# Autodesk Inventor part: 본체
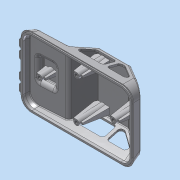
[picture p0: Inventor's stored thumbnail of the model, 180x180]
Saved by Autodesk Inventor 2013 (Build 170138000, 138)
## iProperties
Created: 2015-05
Part Number: 본체
Material: ABS 플라스틱
Document SubType Name: Modeling
Designer: Administrator
Density: 1.06 g/cm^3
Mass: 33.5971 g
Surface Area: 312.398 cm^2
Volume: 31.6954 cm^3
Author: Administrator
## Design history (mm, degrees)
sketch "스케치1"
  geometry: L1 (-60, 0)-(60, 0); L2 (-60, 0)-(-60, 1); L3 (-60, 1)-(60, 1); L4 (60, 1)-(60, 0); L5 (60, 1)-(61, 1); L6 (61, 1)-(58.321, 11); L7 (58.321, 11)-(28.321, 31); L8 (-58.856, 9)-(-19, 11.089); L9 (-19, 11.089)-(-6.558, 31); L10 (-6.558, 31)-(28.321, 31); L11 (-58.856, 9)-(-61, 1); L12 (-61, 1)-(-60, 1); 3 further points
  constraints: 24 end point, 3 parallel, 3 perpendicular, 2 coincident, 2 midpoint, 1 horizontal
  dimensions: "d9" = 120 distance of L1.start L1.end; "d10" = 1 distance of L3.end L1.end; "d11" = 105 deg angle of L6 L1; "d13" = 30 horizontal distance of L6.end L7.end; "d14" = 20 vertical distance of L6.end L7.end; "d15" = 1 distance of L3.end L5.end; "d25" = 1 distance of L11.end L2.end; "d27" = 125 deg angle of L9 L8; "d28" = 3 deg angle of L3 L8; "d29" = 42 horizontal distance of L8.end L11.end; "d30" = 31 distance between parallel lines of L1 L10; "d31" = 9 vertical distance of L1.start L8.start; "d32" = 105 deg angle of L11 L1
extrude "돌출1" new body sketch "스케치1" stored distance "d33" = 76; taper "d34" = 0 deg
extrude "돌출2" join sketch "스케치1" stored distance "d35" = 74; taper "d36" = 0 deg
sketch "스케치3"
  geometry: L1 (1, 38)-(31, 29.962); L2 (1, -38)-(31, -29.962); L3 (31, -38)-(1, -38) reference; L4 (1, -38)-(1, -37) reference; L5 (1, -37)-(0, -37) reference; L6 (0, -37)-(0, 37) reference; L7 (0, 37)-(1, 37) reference; L8 (1, 37)-(1, 38) reference; L9 (1, 38)-(31, 38) reference; L10 (31, 38)-(31, -38) reference; 1 further point
  constraints: 4 end point, 2 point on line
  dimensions: "d41" = 105 deg angle of L2 L6
extrude "돌출4" cut sketch "스케치3" stored distance "d42" = 300; taper "d43" = 0 deg
fillet "모깎기5" dims "d72" = 12
fillet "모깎기6" dims "d73" = 12
fillet "모깎기7" dims "d74" = 3
fillet "모깎기8" dims "d75" = 3
feature "쉘2" dims "d76" = 2
sketch "스케치9"
  geometry: L1 (-36.17, 8.186)-(-36.17, 57.845) reference; L2 (-29.909, 46.016)-(-9.909, 46.016); L3 (-9.909, 46.016)-(-9.909, 20.016); L4 (-9.909, 20.016)-(-29.909, 20.016); L5 (-29.909, 20.016)-(-29.909, 46.016); L6 (-40.909, 59.424)-(-40.909, 6.607) reference; 3 further points
  constraints: 8 end point, 2 midpoint, 2 parallel, 1 horizontal, 1 horizontal alignment, 1 perpendicular
  dimensions: "d77" = 20 distance of L2.start L2.end; "d79" = 26 distance of L4.end L2.start; "d80" = 11 distance between parallel lines of L5 L6
extrude "돌출9" join sketch "스케치9" distance "d81" = 5; taper "d82" = -20 deg
fillet "모깎기9" dims "d83" = 3
fillet "모깎기10" dims "d84" = 3
fillet "모깎기11" dims "d85" = 3
sketch "스케치10"
  geometry: L1 (-60, 1)-(-61, 1) reference; L2 (-61, 1)-(-59.421, 6.895) reference; L3 (-56.68, 9.114)-(-52.525, 9.332) reference; L4 (-49.813, 11.451)-(-49.486, 12.521) reference; L5 (-46.774, 14.64)-(-34.632, 15.276) reference; L6 (-31.713, 13.453)-(-31.276, 12.422) reference; L7 (-28.357, 10.598)-(-20.56, 11.007) reference; L8 (-18.172, 12.413)-(-7.439, 29.59) reference; L9 (-4.895, 31)-(27.412, 31) reference; L10 (29.076, 30.496)-(57.38, 11.627) reference; L11 (58.613, 9.908)-(61, 1) reference; L12 (61, 1)-(60, 1) reference; L13 (60, 1)-(60, 0) reference; L14 (60, 0)-(58, 0) reference; L15 (58, 0)-(58, 3) reference; L16 (58, 3)-(58.394, 3) reference; L17 (58.394, 3)-(56.681, 9.39) reference; L18 (56.27, 9.963)-(27.967, 28.832) reference; L19 (27.412, 29)-(-4.895, 29) reference; L20 (-5.743, 28.53)-(-16.476, 11.353) reference; L21 (-20.455, 9.01)-(-56.575, 7.117) reference; L22 (-57.489, 6.377)-(-58.394, 3) reference; L23 (-58.394, 3)-(-58, 3) reference; L24 (-58, 3)-(-58, 0) reference; L25 (-58, 0)-(-60, 0) reference; L26 (-60, 0)-(-60, 1) reference; L27 (-13.16, 11)-(-3.787, 26); L28 (-3.787, 26)-(17.84, 26); L29 (17.84, 26)-(17.84, 11); L30 (17.84, 11)-(-13.16, 11); L31 (21.307, 26)-(26.807, 26); L32 (26.807, 26)-(49.307, 11); L33 (49.307, 11)-(21.307, 11); L34 (21.307, 11)-(21.307, 26); A1 r 3 centre (-56.523, 6.118) between (-56.68, 9.114) and (-59.421, 6.895) reference; A2 r 3 centre (-52.682, 12.328) between (-52.525, 9.332) and (-49.813, 11.451) reference; A3 r 3 centre (-46.617, 11.644) between (-46.774, 14.64) and (-49.486, 12.521) reference; A4 r 3 centre (-34.474, 12.281) between (-31.713, 13.453) and (-34.632, 15.276) reference; A5 r 3 centre (-28.514, 13.594) between (-31.276, 12.422) and (-28.357, 10.598) reference; A6 r 3 centre (-20.717, 14.003) between (-20.56, 11.007) and (-18.172, 12.413) reference; A7 r 3 centre (-4.895, 28) between (-4.895, 31) and (-7.439, 29.59) reference; A8 r 3 centre (27.412, 28) between (29.076, 30.496) and (27.412, 31) reference; A9 r 3 centre (55.715, 9.131) between (58.613, 9.908) and (57.38, 11.627) reference; A10 r 1 centre (55.715, 9.131) between (56.681, 9.39) and (56.27, 9.963) reference; A11 r 1 centre (27.412, 28) between (27.967, 28.832) and (27.412, 29) reference; A12 r 1 centre (-4.895, 28) between (-4.895, 29) and (-5.743, 28.53) reference; A13 r 5 centre (-20.717, 14.003) between (-20.455, 9.01) and (-16.476, 11.353) reference; A14 r 1 centre (-56.523, 6.118) between (-56.575, 7.117) and (-57.489, 6.377) reference; 1 further point
  constraints: 16 end point, 5 parallel, 3 perpendicular, 1 point on line
  dimensions: "d86" = 5 distance between parallel lines of L27 L8; "d87" = 5 distance between parallel lines of L28 L9; "d89" = 15 distance between parallel lines of L30 L28; "d90" = 31 distance of L29.end L27.start; "d91" = 5 distance between parallel lines of L10 L32; "d92" = 15 distance between parallel lines of L33 L31; "d93" = 28 distance of L32.end L33.end
extrude "돌출10" cut sketch "스케치10" stored distance "d94" = 300; taper "d95" = 0 deg
feature "쉘3" dims "d96" = 2
sketch "스케치13"
  geometry: L1 (65.895, 54.068)-(65.895, 1.251) reference; 2 further points
  constraints: 1 horizontal alignment, 1 other
  dimensions: "d103" = 50 distance from line of point (15.895, 27.66) L1
feature "엠보싱1" sketch "스케치13" dims "d104" = 0.5, "d105" = 0
fillet "모깎기12" dims "d117" = 3
fillet "모깎기13" dims "d118" = 3
sketch "스케치15"
  geometry: L1 (109, -63.409)-(109, -10.591) reference; C1 r 3 at (88, -37); C2 r 3 at (8, -37); C3 r 3 at (48, -15); C4 r 3 at (48, -59); 1 further point
  constraints: 4 centre point, 2 horizontal alignment, 1 vertical alignment
  dimensions: "d119" = 6 diameter of C1; "d120" = 6 diameter of C2; "d121" = 6 diameter of C3; "d122" = 6 diameter of C4; "d123" = 21 distance from line of L1 C1.centre; "d124" = 40 horizontal distance of C3.centre C1.centre; "d125" = 40 horizontal distance of C2.centre C3.centre; "d126" = 22 distance of point (48, -37) C3.centre; "d127" = 22 distance of C4.centre point (48, -37)
extrude "돌출13" join sketch "스케치15" stored distance "d128" = 300; taper "d129" = 2 deg
node "작업 평면4"
sketch "스케치16"
  geometry: L1 (-49.141, 15.732)-(49.141, 15.732) reference; L2 (60.732, 4.141)-(60.732, -48.141) reference; L3 (49.141, -59.732)-(-49.141, -59.732) reference; L4 (-60.732, -48.141)-(-60.732, 4.141) reference; L5 (48, 13)-(-48, 13) reference; L6 (-58, 3)-(-58, -47) reference; L7 (-48, -57)-(48, -57) reference; L8 (58, -47)-(58, 3) reference; L9 (-5, 1)-(5, 1); L10 (5, 1)-(5, -1); L11 (5, -1)-(-5, -1); L12 (-5, -1)-(-5, 1); L13 (-5, 1)-(5, -1); L14 (5, 1)-(-5, -1); C1 r 3.07 at (0, 0) reference; C2 r 3.07 at (40, -22) reference; C3 r 3.07 at (-40, -22) reference; C4 r 3.07 at (0, -44) reference; A1 r 10 centre (48, 3) between (58, 3) and (48, 13) reference; A2 r 10 centre (-48, 3) between (-48, 13) and (-58, 3) reference; A3 r 10 centre (-48, -47) between (-58, -47) and (-48, -57) reference; A4 r 10 centre (48, -47) between (48, -57) and (58, -47) reference; 5 further points; 4 other entities
  constraints: 12 end point, 2 midpoint, 2 parallel, 1 horizontal, 1 perpendicular, 4 other
  dimensions: "d131" = 2 distance of L9.end L10.end; "d133" = 10 distance of L9.start L9.end
extrude "돌출14" join sketch "스케치16" stored distance "d134" = 300; taper "d135" = 5 deg
sketch "스케치17"
  geometry: C1 r 3 at (0, 0) reference; 1 further point
node "작업 평면5"
sketch "스케치18"
  geometry: L1 (35, 23)-(37.098, 23) reference; L2 (45, 21)-(42.902, 21) reference; L3 (45, 23)-(45, 21) reference; L4 (42.902, 23)-(45, 23) reference; L5 (35, 21)-(35, 23) reference; L6 (37.098, 21)-(35, 21) reference; L7 (-9.141, 37.732)-(89.141, 37.732) reference; L8 (100.732, 26.141)-(100.732, -26.141) reference; L9 (89.141, -37.732)-(-9.141, -37.732) reference; L10 (-20.732, -26.141)-(-20.732, 26.141) reference; L11 (88, 35)-(-8, 35) reference; L12 (-18, 25)-(-18, -25) reference; L13 (-8, -35)-(88, -35) reference; L14 (98, -25)-(98, 25) reference; L15 (-5, 1)-(5, 1); L16 (5, 1)-(5, -1); L17 (5, -1)-(-5, -1); L18 (-5, -1)-(-5, 1); L19 (-5, 1)-(5, -1); L20 (5, 1)-(-5, -1); C1 r 3.07 at (80, 0) reference; C2 r 3.07 at (0, 0) reference; C3 r 3.07 at (40, -22) reference; A1 r 3.07 centre (40, 22) between (37.098, 23) and (37.098, 21) reference; A2 r 3.07 centre (40, 22) between (37.098, 21) and (42.902, 21) reference; A3 r 3.07 centre (40, 22) between (42.902, 21) and (42.902, 23) reference; A4 r 3.07 centre (40, 22) between (42.902, 23) and (37.098, 23) reference; A5 r 10 centre (88, 25) between (98, 25) and (88, 35) reference; A6 r 10 centre (-8, 25) between (-8, 35) and (-18, 25) reference; A7 r 10 centre (-8, -25) between (-18, -25) and (-8, -35) reference; A8 r 10 centre (88, -25) between (88, -35) and (98, -25) reference; 5 further points; 4 other entities
  constraints: 12 end point, 2 midpoint, 2 parallel, 1 horizontal, 1 perpendicular, 4 other
  dimensions: "d137" = 10 distance of L16.end L17.end; "d138" = 2 distance of L15.end L16.end
extrude "돌출15" join sketch "스케치18" stored distance "d139" = 300; taper "d140" = 5 deg
node "작업 평면6"
sketch "스케치19"
  geometry: L1 (-35, 21)-(-37.098, 21) reference; L2 (-42.902, 21)-(-45, 21) reference; L3 (-45, 21)-(-45, 23) reference; L4 (-45, 23)-(-42.902, 23) reference; L5 (-37.098, 23)-(-35, 23) reference; L6 (-35, 23)-(-35, 21) reference; L7 (-5, 45)-(-2.902, 45) reference; L8 (5, 43)-(2.902, 43) reference; L9 (5, 45)-(5, 43) reference; L10 (2.902, 45)-(5, 45) reference; L11 (-5, 43)-(-5, 45) reference; L12 (-2.902, 43)-(-5, 43) reference; L13 (-49.141, 59.732)-(49.141, 59.732) reference; L14 (60.732, 48.141)-(60.732, -4.141) reference; L15 (49.141, -15.732)-(-49.141, -15.732) reference; L16 (-60.732, -4.141)-(-60.732, 48.141) reference; L17 (48, 57)-(-48, 57) reference; L18 (-58, 47)-(-58, -3) reference; L19 (-48, -13)-(48, -13) reference; L20 (58, -3)-(58, 47) reference; L21 (-5, 1)-(5, 1); L22 (5, 1)-(5, -1); L23 (5, -1)-(-5, -1); L24 (-5, -1)-(-5, 1); L25 (-5, 1)-(5, -1); L26 (5, 1)-(-5, -1); C1 r 3.07 at (40, 22) reference; C2 r 3.07 at (0, 0) reference; A1 r 3.07 centre (-40, 22) between (-42.902, 21) and (-37.098, 21) reference; A2 r 3.07 centre (-40, 22) between (-37.098, 23) and (-42.902, 23) reference; A3 r 3.07 centre (-40, 22) between (-37.098, 21) and (-37.098, 23) reference; A4 r 3.07 centre (-40, 22) between (-42.902, 23) and (-42.902, 21) reference; A5 r 3.07 centre (0, 44) between (-2.902, 45) and (-2.902, 43) reference; A6 r 3.07 centre (0, 44) between (-2.902, 43) and (2.902, 43) reference; A7 r 3.07 centre (0, 44) between (2.902, 43) and (2.902, 45) reference; A8 r 3.07 centre (0, 44) between (2.902, 45) and (-2.902, 45) reference; A9 r 10 centre (48, 47) between (58, 47) and (48, 57) reference; A10 r 10 centre (-48, 47) between (-48, 57) and (-58, 47) reference; A11 r 10 centre (-48, -3) between (-58, -3) and (-48, -13) reference; A12 r 10 centre (48, -3) between (48, -13) and (58, -3) reference; 5 further points; 4 other entities
  constraints: 12 end point, 2 midpoint, 2 parallel, 1 horizontal, 1 perpendicular, 4 other
  dimensions: "d142" = 10 distance of L22.end L23.end; "d143" = 2 distance of L21.end L22.end
extrude "돌출16" join sketch "스케치19" stored distance "d144" = 300; taper "d145" = 5 deg
node "작업 평면7"
sketch "스케치20"
  geometry: L1 (-35, -23)-(-37.098, -23) reference; L2 (-42.902, -23)-(-45, -23) reference; L3 (-45, -23)-(-45, -21) reference; L4 (-45, -21)-(-42.902, -21) reference; L5 (-37.098, -21)-(-35, -21) reference; L6 (-35, -21)-(-35, -23) reference; L7 (-75, -1)-(-77.098, -1) reference; L8 (-82.902, -1)-(-85, -1) reference; L9 (-85, -1)-(-85, 1) reference; L10 (-85, 1)-(-82.902, 1) reference; L11 (-77.098, 1)-(-75, 1) reference; L12 (-75, 1)-(-75, -1) reference; L13 (-45, 23)-(-42.902, 23) reference; L14 (-35, 21)-(-37.098, 21) reference; L15 (-35, 23)-(-35, 21) reference; L16 (-37.098, 23)-(-35, 23) reference; L17 (-45, 21)-(-45, 23) reference; L18 (-42.902, 21)-(-45, 21) reference; L19 (-89.141, 37.732)-(9.141, 37.732) reference; L20 (20.732, 26.141)-(20.732, -26.141) reference; L21 (9.141, -37.732)-(-89.141, -37.732) reference; L22 (-100.732, -26.141)-(-100.732, 26.141) reference; L23 (8, 35)-(-88, 35) reference; L24 (-98, 25)-(-98, -25) reference; L25 (-88, -35)-(8, -35) reference; L26 (18, -25)-(18, 25) reference; L27 (-5, 1)-(5, 1); L28 (5, 1)-(5, -1); L29 (5, -1)-(-5, -1); L30 (-5, -1)-(-5, 1); L31 (-5, 1)-(5, -1); L32 (5, 1)-(-5, -1); C1 r 3.07 at (0, 0) reference; A1 r 3.07 centre (-40, -22) between (-42.902, -23) and (-37.098, -23) reference; A2 r 3.07 centre (-40, -22) between (-37.098, -21) and (-42.902, -21) reference; A3 r 3.07 centre (-40, -22) between (-37.098, -23) and (-37.098, -21) reference; A4 r 3.07 centre (-40, -22) between (-42.902, -21) and (-42.902, -23) reference; A5 r 3.07 centre (-80, 0) between (-82.902, -1) and (-77.098, -1) reference; A6 r 3.07 centre (-80, 0) between (-77.098, 1) and (-82.902, 1) reference; A7 r 3.07 centre (-80, 0) between (-77.098, -1) and (-77.098, 1) reference; A8 r 3.07 centre (-80, 0) between (-82.902, 1) and (-82.902, -1) reference; A9 r 3.07 centre (-40, 22) between (-42.902, 23) and (-42.902, 21) reference; A10 r 3.07 centre (-40, 22) between (-42.902, 21) and (-37.098, 21) reference; A11 r 3.07 centre (-40, 22) between (-37.098, 21) and (-37.098, 23) reference; A12 r 3.07 centre (-40, 22) between (-37.098, 23) and (-42.902, 23) reference; A13 r 10 centre (8, 25) between (18, 25) and (8, 35) reference; A14 r 10 centre (-88, 25) between (-88, 35) and (-98, 25) reference; A15 r 10 centre (-88, -25) between (-98, -25) and (-88, -35) reference; A16 r 10 centre (8, -25) between (8, -35) and (18, -25) reference; 5 further points; 4 other entities
  constraints: 12 end point, 2 midpoint, 2 parallel, 1 horizontal, 1 perpendicular, 4 other
  dimensions: "d147" = 10 distance of L28.end L29.end; "d148" = 2 distance of L27.end L28.end
extrude "돌출17" join sketch "스케치20" stored distance "d149" = 300; taper "d150" = 5 deg
sketch "스케치21"
  geometry: C1 r 3 at (0, 0) reference; C2 r 3 at (-40, -22) reference; C3 r 3 at (0, -44) reference; C4 r 3 at (40, -22) reference; 1 further point
hole "구멍1" sketch "스케치21" at (0, 0), (40, -22), (0, -44), (-40, -22) diameter "d151" = 3.242; stored, may be unused: countersink angle "d155" = 90 deg, drill point angle "d157" = 118 deg; dims "d152" = 9, "d153" = 4, "d154" = 2, "d156" = 11
node "작업 평면9"
  node "작업 평면8"
sketch "스케치22"
  geometry: A1 r 4 centre (-1, -21) between (-1, -17) and (-1, -25); A2 r 4 centre (-1, -10) between (-1, -6) and (-1, -14); A3 r 4 centre (-1, 10) between (-1, 14) and (-1, 6); A4 r 4 centre (-1, 21) between (-1, 25) and (-1, 17); 4 further points
  constraints: 8 point on circle, 4 centre point, 4 vertical alignment, 14 other
  dimensions: "d160" = 8 diameter of A1; "d161" = 8 diameter of A2; "d162" = 8 diameter of A3; "d163" = 8 diameter of A4; "d164" = 10 distance of A3.centre point (-1, 0); "d165" = 11 distance of A4.centre A3.centre; "d166" = 10 distance of A2.centre point (-1, 0); "d167" = 11 distance of A1.centre A2.centre
extrude "돌출18" join sketch "스케치22" stored distance "d168" = 10; taper "d169" = 0 deg
chamfer "모따기1" distance "d170" = 1; stored, may be unused: second distance "d171" = 2, angle "d172" = 45 deg
feature "쉘1" dims "d47" = 2
sketch "스케치5"
  geometry: L1 (-61, 1)-(-58.856, 9) reference; L2 (-58.856, 9)-(-19, 11.089) reference; L3 (-19, 11.089)-(-6.558, 31) reference; L4 (-6.558, 31)-(28.321, 31) reference; L5 (28.321, 31)-(58.321, 11) reference; L6 (58.321, 11)-(61, 1) reference; L7 (61, 1)-(60, 1) reference; L8 (60, 1)-(60, 0) reference; L9 (60, 0)-(59, 0) reference; L10 (59, 0)-(59, 1) reference; L11 (59, 1)-(58, 1) reference; L12 (58, 1)-(58, 3) reference; L13 (58, 3)-(58.394, 3) reference; L14 (58.394, 3)-(56.584, 9.754) reference; L15 (56.584, 9.754)-(27.715, 29) reference; L16 (27.715, 29)-(-5.449, 29) reference; L17 (-5.449, 29)-(-17.856, 9.146) reference; L18 (-17.856, 9.146)-(-57.301, 7.079) reference; L19 (-57.301, 7.079)-(-58.394, 3) reference; L20 (-58.394, 3)-(-58, 3) reference; L21 (-58, 3)-(-58, 1) reference; L22 (-58, 1)-(-59, 1) reference; L23 (-59, 1)-(-59, 0) reference; L24 (-59, 0)-(-60, 0) reference; L25 (-60, 0)-(-60, 1) reference; L26 (-60, 1)-(-61, 1) reference; L27 (-58.394, 3)-(-58.929, 1); L28 (58.394, 3)-(58.929, 1); 1 further point
  constraints: 4 end point, 2 collinear, 2 point on line
extrude "돌출5" cut sketch "스케치5" stored distance "d48" = 70; taper "d49" = 0 deg
node "솔리드1"
node "투영된 루프2"
node "투영된 루프3"
node "절단 모서리 투영1"
node "절단 모서리 투영3"
node "절단 모서리 투영5"
node "절단 모서리 투영6"
node "절단 모서리 투영7"
node "절단 모서리 투영8"
node "절단 모서리 투영9"
other parameters: "d130" = -2, "d136" = -2, "d141" = -2, "d146" = -2, "d158" = -61, "d159" = -2
